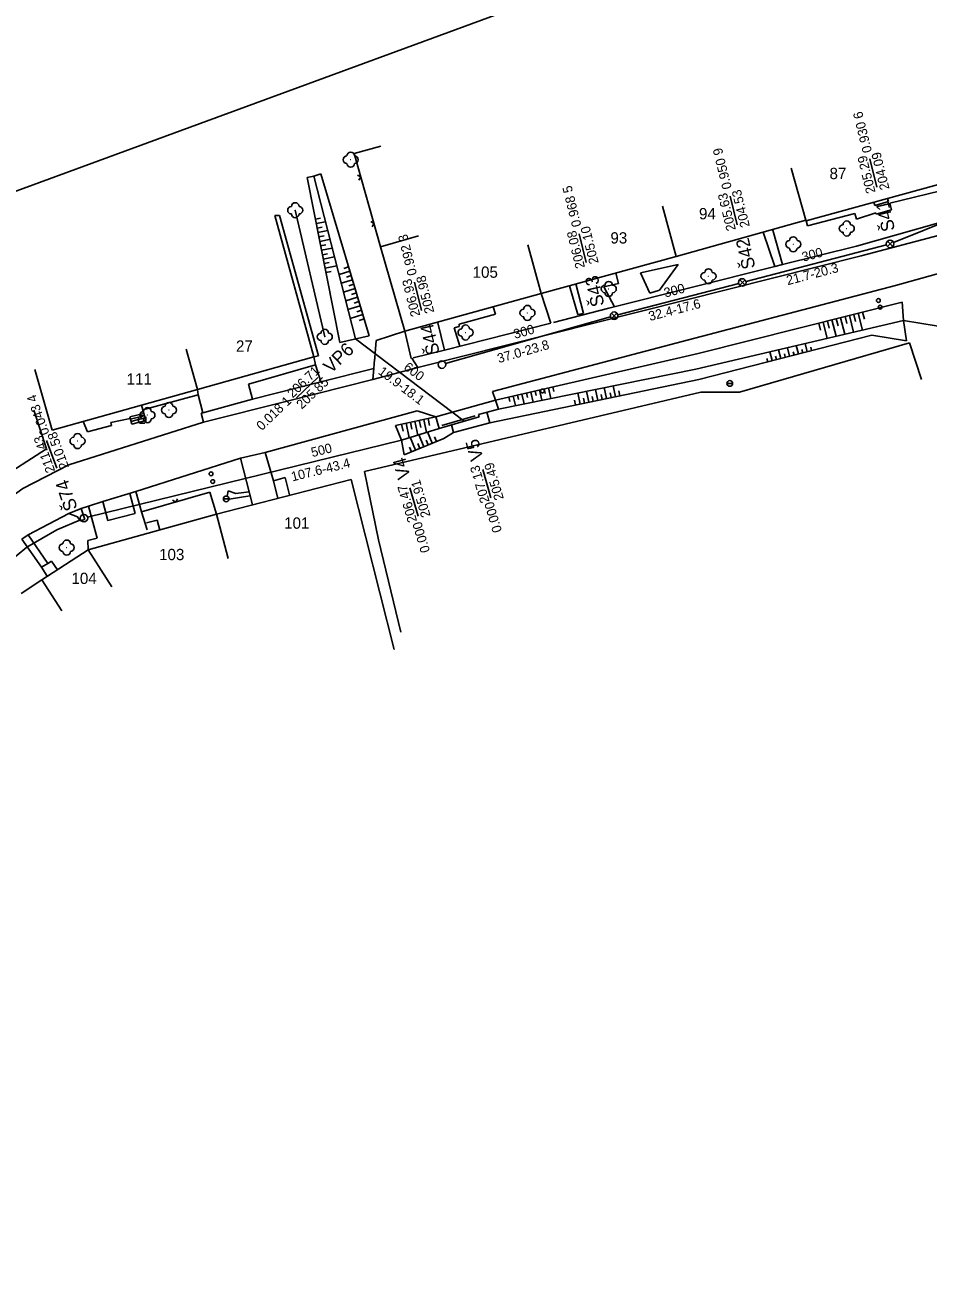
# Model space of a CAD drawing. Extents: x -574526 to -573537, y -1188297 to -1187280.
# Drawn here: x -574440.8 to -574321, y -1188129.5 to -1187965.1 of the extents above; entities that cross this region are included whole.
import ezdxf

# ---------------------------------------------------------------- set-up
doc = ezdxf.new("R2010")
doc.units = 0
for name, color, linetype in [('Vrstva 10', 7, 'Continuous'), ('Vrstva 12', 7, 'Continuous'), ('Vrstva 13', 7, 'Continuous'), ('Vrstva 14', 7, 'Continuous'), ('Vrstva 17', 7, 'Continuous'), ('Vrstva 18', 7, 'Continuous'), ('Vrstva 2', 7, 'Continuous'), ('Vrstva 21', 7, 'Continuous'), ('Vrstva 4', 7, 'Continuous'), ('Vrstva 6', 7, 'Continuous'), ('Vrstva 63', 7, 'Continuous'), ('Vrstva 7', 7, 'Continuous'), ('Vrstva 8', 7, 'Continuous'), ('Vrstva 9', 7, 'Continuous')]:
    doc.layers.add(name, color=color, linetype=linetype)

# ---------------------------------------------------------------- blocks, each defined once
blk = doc.blocks.new('3$130')
at = {"layer": 'Vrstva 8'}
blk.add_circle((0, 0), 0.001, dxfattribs=at)
for centre, start, end in [((-1, 0), 90, 270), ((0, 1), 0, 180), ((1, 0), 270, 90), ((0, -1), 180, 0)]:
    blk.add_arc(centre, 1, start, end, dxfattribs=at)
blk = doc.blocks.new('8$110')
at = {"layer": 'Vrstva 6'}
blk.add_line((-0.75, 0), (0.75, 0), dxfattribs=at)
blk.add_circle((0, 0), 0.75, dxfattribs=at)
blk = doc.blocks.new('6$010')
at = {"layer": 'Vrstva 21'}
blk.add_circle((0, 0), 0.5, dxfattribs=at)
blk = doc.blocks.new('6$091')
at = {"layer": 'Vrstva 21'}
for p, q in [((-1, 0.7), (-1, -0.7)), ((0.7, 1), (-0.7, 1)), ((1, -0.7), (1, 0.7)), ((-0.7, -1), (0.7, -1))]:
    blk.add_line(p, q, dxfattribs=at)
blk = doc.blocks.new('200')
at = {"layer": 'Vrstva 63'}
blk.add_lwpolyline([(0, 0), (210, 0), (210, 297), (0, 297), (0, 0)], close=True, dxfattribs=at)

msp = doc.modelspace()

# ---------------------------------------------------------------- linework, layer by layer
at = {"layer": 'Vrstva 10'}
for p, q in [((-574402.48, -1187985.21), (-574403.39, -1187985.39)), ((-574401.57, -1187984.87), (-574402.48, -1187985.21)), ((-574396.97, -1188006.77), (-574402.48, -1187985.21)), ((-574395.16, -1188006.36), (-574401.57, -1187984.87)), ((-574403.39, -1187985.39), (-574399.05, -1188007.24)), ((-574401.61, -1187990.77), (-574402.29, -1187990.9)), ((-574400.94, -1187991.25), (-574402.18, -1187991.49)), ((-574401.38, -1187991.95), (-574402.06, -1187992.08)), ((-574400.64, -1187992.41), (-574401.94, -1187992.67)), ((-574401.14, -1187993.12), (-574401.83, -1187993.26)), ((-574400.3, -1187993.57), (-574401.71, -1187993.85)), ((-574400.91, -1187994.3), (-574401.59, -1187994.43)), ((-574400.05, -1187994.74), (-574401.48, -1187995.03)), ((-574400.68, -1187995.48), (-574401.36, -1187995.61)), ((-574399.75, -1187995.91), (-574401.24, -1187996.2)), ((-574400.44, -1187996.65), (-574401.13, -1187996.79)), ((-574399.45, -1187997.07), (-574401.01, -1187997.38)), ((-574400.21, -1187997.83), (-574400.89, -1187997.97)), ((-574399.15, -1187998.24), (-574397.71, -1187997.81)), ((-574398.52, -1187997.42), (-574397.88, -1187997.23)), ((-574398.85, -1187999.4), (-574397.37, -1187998.96)), ((-574398.17, -1187998.57), (-574397.54, -1187998.38)), ((-574397.83, -1187999.72), (-574397.19, -1187999.53)), ((-574398.56, -1188000.56), (-574397.02, -1188000.11)), ((-574398.26, -1188001.73), (-574396.68, -1188001.26)), ((-574397.49, -1188000.87), (-574396.85, -1188000.68)), ((-574397.96, -1188002.89), (-574396.34, -1188002.41)), ((-574397.15, -1188002.02), (-574396.51, -1188001.83)), ((-574396.8, -1188003.17), (-574396.17, -1188002.98)), ((-574324.45, -1188001.92), (-574351.5, -1188008.72)), ((-574329.45, -1188004.17), (-574329.69, -1188003.23)), ((-574324.24, -1188004.33), (-574324.45, -1188001.92)), ((-574397.67, -1188004.06), (-574396, -1188003.56)), ((-574396.46, -1188004.32), (-574395.82, -1188004.13)), ((-574351.79, -1188010.78), (-574324.24, -1188004.33)), ((-574335.27, -1188005.63), (-574335.51, -1188004.7)), ((-574334.38, -1188006.71), (-574334.92, -1188004.55)), ((-574334.11, -1188005.34), (-574334.34, -1188004.41)), ((-574333.21, -1188006.43), (-574333.76, -1188004.26)), ((-574332.94, -1188005.05), (-574333.18, -1188004.11)), ((-574332.05, -1188006.16), (-574332.6, -1188003.97)), ((-574331.78, -1188004.75), (-574332.01, -1188003.82)), ((-574330.88, -1188005.88), (-574331.43, -1188003.67)), ((-574330.62, -1188004.46), (-574330.85, -1188003.53)), ((-574329.71, -1188005.61), (-574330.27, -1188003.38)), ((-574324.24, -1188004.33), (-574323.85, -1188007.05)), ((-574399.05, -1188007.24), (-574395.16, -1188006.36)), ((-574328.47, -1188006.27), (-574351.41, -1188012.16)), ((-574323.85, -1188007.05), (-574328.47, -1188006.27)), ((-574340.82, -1188008.21), (-574340.52, -1188009.37)), ((-574339.65, -1188007.94), (-574339.36, -1188009.07)), ((-574338.48, -1188007.67), (-574338.2, -1188008.77)), ((-574337.73, -1188008.17), (-574337.62, -1188008.62)), ((-574337.31, -1188007.39), (-574337.04, -1188008.47)), ((-574336.57, -1188007.87), (-574336.46, -1188008.32)), ((-574351.5, -1188008.72), (-574378.37, -1188014.89)), ((-574342.38, -1188009.36), (-574342.27, -1188009.81)), ((-574341.99, -1188008.49), (-574341.69, -1188009.66)), ((-574341.22, -1188009.06), (-574341.11, -1188009.51)), ((-574340.06, -1188008.76), (-574339.94, -1188009.21)), ((-574338.89, -1188008.47), (-574338.78, -1188008.91)), ((-574378.01, -1188016.08), (-574351.79, -1188010.78)), ((-574351.41, -1188012.16), (-574379.15, -1188017.9)), ((-574370.64, -1188013.75), (-574370.78, -1188013.15)), ((-574362.77, -1188013), (-574362.47, -1188014.45)), ((-574376.49, -1188015.09), (-574376.63, -1188014.49)), ((-574375.75, -1188015.62), (-574376.05, -1188014.36)), ((-574375.32, -1188014.82), (-574375.46, -1188014.22)), ((-574374.58, -1188015.39), (-574374.88, -1188014.09)), ((-574374.15, -1188014.55), (-574374.29, -1188013.95)), ((-574373.4, -1188015.15), (-574373.71, -1188013.82)), ((-574372.98, -1188014.28), (-574373.12, -1188013.69)), ((-574372.22, -1188014.91), (-574372.54, -1188013.55)), ((-574371.81, -1188014.01), (-574371.95, -1188013.41)), ((-574371.05, -1188014.67), (-574371.37, -1188013.28)), ((-574367.48, -1188013.95), (-574367.17, -1188015.42)), ((-574366.72, -1188014.65), (-574366.59, -1188015.3)), ((-574366.3, -1188013.71), (-574366, -1188015.18)), ((-574365.55, -1188014.4), (-574365.41, -1188015.06)), ((-574365.12, -1188013.47), (-574364.82, -1188014.93)), ((-574364.37, -1188014.16), (-574364.23, -1188014.81)), ((-574363.95, -1188013.24), (-574363.65, -1188014.69)), ((-574363.19, -1188013.92), (-574363.06, -1188014.57)), ((-574362.02, -1188013.67), (-574361.88, -1188014.33)), ((-574367.89, -1188014.89), (-574367.76, -1188015.54)), ((-574391.67, -1188018.24), (-574386.32, -1188017.11)), ((-574390.65, -1188019.01), (-574390.85, -1188018.07)), ((-574389.85, -1188019.88), (-574390.26, -1188017.94)), ((-574389.48, -1188018.76), (-574389.67, -1188017.82)), ((-574388.7, -1188019.53), (-574389.09, -1188017.69)), ((-574388.3, -1188018.51), (-574388.5, -1188017.57)), ((-574387.55, -1188019.17), (-574387.91, -1188017.45)), ((-574387.13, -1188018.26), (-574387.33, -1188017.32)), ((-574390.88, -1188020.2), (-574391.67, -1188018.24)), ((-574390.88, -1188020.2), (-574385.88, -1188018.65)), ((-574388.54, -1188019.47), (-574387.89, -1188021.07)), ((-574387.39, -1188019.12), (-574386.78, -1188020.61)), ((-574385.23, -1188019.98), (-574383.95, -1188019.18)), ((-574390.5, -1188022.14), (-574390.88, -1188020.2)), ((-574390.5, -1188022.14), (-574385.23, -1188019.98)), ((-574389.81, -1188021.12), (-574389.55, -1188021.75)), ((-574389.69, -1188019.83), (-574389, -1188021.53)), ((-574388.7, -1188020.67), (-574388.44, -1188021.3)), ((-574387.59, -1188020.22), (-574387.33, -1188020.84)), ((-574386.48, -1188019.76), (-574386.22, -1188020.39))]:
    msp.add_line(p, q, dxfattribs=at)
at = {"layer": 'Vrstva 13'}
for p, q in [((-574327.81, -1187986.66), (-574328.74, -1187982.88)), ((-574346.33, -1187991.65), (-574347.27, -1187987.86)), ((-574366.36, -1187996.64), (-574367.3, -1187992.85)), ((-574388.21, -1188003.03), (-574389.15, -1187999.25)), ((-574404.78, -1188014.61), (-574401.97, -1188011.9)), ((-574436.61, -1188023.92), (-574437.94, -1188020.25)), ((-574378.99, -1188027.84), (-574380.09, -1188024.1)), ((-574388.66, -1188030.29), (-574389.76, -1188026.54))]:
    msp.add_line(p, q, dxfattribs=at)
at = {"layer": 'Vrstva 17'}
for p, q in [((-574326.39, -1187994.53), (-574325.69, -1187993.82)), ((-574326.39, -1187993.82), (-574325.69, -1187994.53)), ((-574345.99, -1187999.64), (-574345.28, -1187998.94)), ((-574345.99, -1187998.94), (-574345.28, -1187999.64)), ((-574363, -1188004.05), (-574362.29, -1188003.35)), ((-574363, -1188003.35), (-574362.29, -1188004.05))]:
    msp.add_line(p, q, dxfattribs=at)
at = {"layer": 'Vrstva 2'}
for p, q in [((-574325.58, -1187993.99), (-574296.46, -1187982.19)), ((-574345.15, -1187999.16), (-574326.52, -1187994.3)), ((-574362.16, -1188003.57), (-574346.12, -1187999.41)), ((-574385.02, -1188010.05), (-574363.13, -1188003.84)), ((-574324.24, -1188004.33), (-574317.75, -1188005.4)), ((-574396.97, -1188006.77), (-574382.54, -1188017.69)), ((-574432.51, -1188030.43), (-574390.88, -1188020.2))]:
    msp.add_line(p, q, dxfattribs=at)
msp.add_lwpolyline([(-574466.04, -1188068.94), (-574458.4, -1188054.44), (-574455.1, -1188048.91), (-574451.58, -1188044.6), (-574447.05, -1188039.72), (-574440.59, -1188034.41), (-574436.57, -1188032.11), (-574433.45, -1188030.75)], dxfattribs=at)
at = {"layer": 'Vrstva 4'}
for p, q in [((-574401.04, -1188006.5), (-574404.96, -1187989.71)), ((-574354.16, -1187996.91), (-574359.15, -1187998.03)), ((-574359.15, -1187998.03), (-574357.93, -1188000.73)), ((-574356.61, -1188000.31), (-574354.16, -1187996.91)), ((-574357.93, -1188000.73), (-574356.61, -1188000.31)), ((-574346.02, -1188013.83), (-574323.46, -1188007.29)), ((-574323.46, -1188007.29), (-574321.88, -1188012.16)), ((-574395.77, -1188024.35), (-574351.16, -1188013.86)), ((-574351.16, -1188013.86), (-574346.02, -1188013.83)), ((-574437.95, -1188021.35), (-574439.66, -1188016.24)), ((-574449.5, -1188028.77), (-574437.95, -1188021.35)), ((-574393.9, -1188033.41), (-574395.77, -1188024.35)), ((-574393.9, -1188033.41), (-574390.96, -1188045.67))]:
    msp.add_line(p, q, dxfattribs=at)
at = {"layer": 'Vrstva 6'}
for p, q in [((-574393.6, -1187981.21), (-574397.14, -1187982.21)), ((-574393.65, -1187994.55), (-574397.14, -1187982.21)), ((-574326.38, -1187988.15), (-574326.26, -1187988.55)), ((-574328.19, -1187988.65), (-574328.06, -1187989.08)), ((-574328.06, -1187989.08), (-574326.26, -1187988.55)), ((-574371.05, -1188004.69), (-574372.31, -1188000.76)), ((-574390.44, -1188005.74), (-574389.57, -1188009.36)), ((-574401.58, -1188012.49), (-574402.26, -1188010.22)), ((-574410.63, -1188014.75), (-574401.58, -1188012.49)), ((-574378.01, -1188016.08), (-574380.65, -1188016.82)), ((-574378.37, -1188014.89), (-574378.01, -1188016.08)), ((-574425.06, -1188016.67), (-574426.92, -1188017.13)), ((-574426.92, -1188017.13), (-574426.66, -1188018.07)), ((-574424.99, -1188016.96), (-574426.85, -1188017.42)), ((-574424.91, -1188017.25), (-574426.77, -1188017.71)), ((-574424.8, -1188017.61), (-574426.66, -1188018.07)), ((-574425.06, -1188016.67), (-574424.8, -1188017.61)), ((-574386.32, -1188017.11), (-574385.88, -1188018.65)), ((-574380.56, -1188017.13), (-574385.88, -1188018.65)), ((-574385.49, -1188018.26), (-574381.08, -1188017)), ((-574383.95, -1188019.18), (-574379.15, -1188017.9)), ((-574380.65, -1188016.82), (-574380.56, -1188017.13)), ((-574379.52, -1188016.5), (-574379.15, -1188017.9)), ((-574384.22, -1188018.17), (-574383.95, -1188019.18)), ((-574425.36, -1188029.7), (-574416.27, -1188027.11)), ((-574416.27, -1188027.11), (-574415.39, -1188030.02)), ((-574424.62, -1188032.08), (-574425.36, -1188029.7)), ((-574441.31, -1188040.56), (-574438.57, -1188038.71))]:
    msp.add_line(p, q, dxfattribs=at)
for points in [[(-574396.51, -1187985.73), (-574396.27, -1187985.29), (-574396.7, -1187985.05)], [(-574394.76, -1187991.9), (-574394.52, -1187991.47), (-574394.95, -1187991.22)], [(-574421.25, -1188028.16), (-574420.82, -1188028.41), (-574420.57, -1188027.97)]]:
    msp.add_lwpolyline(points, dxfattribs=at)
at = {"layer": 'Vrstva 7'}
for p, q in [((-574339.16, -1187984.13), (-574337.23, -1187991.01)), ((-574317.85, -1187985.82), (-574337.19, -1187991.11)), ((-574356.24, -1187989.18), (-574354.41, -1187995.83)), ((-574407.66, -1187990.42), (-574402.49, -1188009.14)), ((-574337.23, -1187991.01), (-574354.41, -1187995.83)), ((-574337.19, -1187991.11), (-574337.23, -1187991.01)), ((-574388.62, -1187993.11), (-574393.65, -1187994.55)), ((-574390.44, -1188005.74), (-574393.65, -1187994.55)), ((-574374.09, -1187994.29), (-574372.31, -1188000.76)), ((-574354.41, -1187995.83), (-574372.31, -1188000.76)), ((-574372.31, -1188000.76), (-574390.44, -1188005.74)), ((-574419.41, -1188008.12), (-574417.91, -1188013.49)), ((-574402.49, -1188009.14), (-574417.91, -1188013.49)), ((-574439.5, -1188010.84), (-574437.19, -1188018.89)), ((-574417.91, -1188013.49), (-574437.19, -1188018.89)), ((-574415.39, -1188030.02), (-574397.53, -1188025.42)), ((-574391.85, -1188047.95), (-574397.53, -1188025.42)), ((-574432.42, -1188034.76), (-574415.39, -1188030.02)), ((-574413.88, -1188035.89), (-574415.39, -1188030.02)), ((-574438.57, -1188038.71), (-574432.42, -1188034.76)), ((-574429.28, -1188039.65), (-574432.42, -1188034.76)), ((-574435.92, -1188042.83), (-574438.57, -1188038.71))]:
    msp.add_line(p, q, dxfattribs=at)
at = {"layer": 'Vrstva 8'}
for centre in [(-574326.04, -1187994.18), (-574345.64, -1187999.29), (-574362.65, -1188003.7), (-574385.5, -1188010.19), (-574432.99, -1188030.55)]:
    msp.add_circle(centre, 0.5, dxfattribs=at)
at = {"layer": 'Vrstva 9'}
for p, q in [((-574317.7, -1187986.76), (-574326.05, -1187988.76)), ((-574330.72, -1187990.14), (-574336.99, -1187991.78)), ((-574330.51, -1187990.89), (-574330.72, -1187990.14)), ((-574327.94, -1187990.08), (-574330.51, -1187990.89)), ((-574327.87, -1187990.24), (-574327.94, -1187990.08)), ((-574325.84, -1187989.66), (-574327.87, -1187990.24)), ((-574326.05, -1187988.76), (-574325.84, -1187989.66)), ((-574407.05, -1187990.4), (-574407.66, -1187990.42)), ((-574401.86, -1188009.01), (-574407.05, -1187990.4)), ((-574336.99, -1187991.78), (-574337.19, -1187991.11)), ((-574315.93, -1187990.34), (-574330.49, -1187994.49)), ((-574341.33, -1187997.18), (-574342.88, -1187992.63)), ((-574341.61, -1187992.34), (-574340.32, -1187996.93)), ((-574330.49, -1187994.49), (-574340.32, -1187996.93)), ((-574329.89, -1187995.75), (-574388.71, -1188010.59)), ((-574325.32, -1187999.69), (-574312.62, -1187996.17)), ((-574341.33, -1187997.18), (-574363.37, -1188002.71)), ((-574362.42, -1187998.04), (-574362.05, -1187999.43)), ((-574340.32, -1187996.93), (-574341.33, -1187997.18)), ((-574367.48, -1188003.54), (-574368.59, -1187999.74)), ((-574367.71, -1187999.49), (-574366.7, -1188003.41)), ((-574362.05, -1187999.43), (-574364.01, -1187999.87)), ((-574362.61, -1188002.52), (-574364.01, -1187999.87)), ((-574352.77, -1188006.89), (-574325.32, -1187999.69)), ((-574378.68, -1188002.51), (-574378.41, -1188003.49)), ((-574363.37, -1188002.71), (-574370.71, -1188004.59)), ((-574386.03, -1188004.63), (-574385.14, -1188008.29)), ((-574378.41, -1188003.49), (-574383.22, -1188004.83)), ((-574383.19, -1188005.15), (-574383.22, -1188004.83)), ((-574371.05, -1188004.69), (-574382.38, -1188007.55)), ((-574366.7, -1188003.41), (-574367.48, -1188003.54)), ((-574390.44, -1188005.74), (-574394.21, -1188006.99)), ((-574383.86, -1188005.3), (-574383.19, -1188005.15)), ((-574383.86, -1188005.3), (-574383.1, -1188007.74)), ((-574394.21, -1188006.99), (-574394.46, -1188009.79)), ((-574382.38, -1188007.55), (-574385.14, -1188008.29)), ((-574378.78, -1188013.74), (-574352.77, -1188006.89)), ((-574402.49, -1188009.14), (-574401.86, -1188009.01)), ((-574402.49, -1188009.14), (-574402.26, -1188010.22)), ((-574394.43, -1188009.48), (-574394.54, -1188010.7)), ((-574388.71, -1188010.59), (-574389.5, -1188009.34)), ((-574385.14, -1188008.29), (-574389.32, -1188009.29)), ((-574402.26, -1188010.22), (-574411.17, -1188012.78)), ((-574394.54, -1188010.7), (-574401.58, -1188012.49)), ((-574394.65, -1188012.15), (-574388.71, -1188010.59)), ((-574394.54, -1188010.7), (-574394.65, -1188012.15)), ((-574411.17, -1188012.78), (-574410.63, -1188014.75)), ((-574394.65, -1188012.15), (-574406.04, -1188015.02)), ((-574425.19, -1188016.19), (-574417.83, -1188014.21)), ((-574417.83, -1188014.21), (-574417.91, -1188013.49)), ((-574417.83, -1188014.21), (-574417.22, -1188016.57)), ((-574410.63, -1188014.75), (-574417.22, -1188016.57)), ((-574378.37, -1188014.89), (-574378.78, -1188013.74)), ((-574425.06, -1188016.67), (-574425.36, -1188015.58)), ((-574406.04, -1188015.02), (-574417.13, -1188017.82)), ((-574408.96, -1188021.82), (-574388.76, -1188016.33)), ((-574388.76, -1188016.33), (-574386.32, -1188017.11)), ((-574378.37, -1188014.89), (-574386.32, -1188017.11)), ((-574417.13, -1188017.82), (-574435.01, -1188023.49)), ((-574433.08, -1188017.74), (-574432.52, -1188019.1)), ((-574429.44, -1188017.88), (-574426.87, -1188017.32)), ((-574429.33, -1188018.28), (-574429.44, -1188017.88)), ((-574417.42, -1188016.63), (-574417.22, -1188016.57)), ((-574417.42, -1188016.63), (-574417.13, -1188017.82)), ((-574432.52, -1188019.1), (-574429.33, -1188018.28)), ((-574426.13, -1188027.03), (-574412.2, -1188022.6)), ((-574412.2, -1188022.6), (-574408.96, -1188021.82)), ((-574412.2, -1188022.6), (-574410.64, -1188028.8)), ((-574408.96, -1188021.82), (-574407.85, -1188025.58)), ((-574407.85, -1188025.58), (-574406.28, -1188025.17)), ((-574407.85, -1188025.58), (-574407.28, -1188027.93)), ((-574406.28, -1188025.17), (-574405.73, -1188027.45)), ((-574430.5, -1188028.34), (-574426.13, -1188027.03)), ((-574426.18, -1188029.91), (-574426.92, -1188027.27)), ((-574426.13, -1188027.03), (-574425.36, -1188029.7)), ((-574413.98, -1188027.63), (-574413.85, -1188026.93)), ((-574413.85, -1188026.93), (-574412.84, -1188027.3)), ((-574411, -1188027.59), (-574413.73, -1188028.04)), ((-574412.84, -1188027.3), (-574411.08, -1188027.05)), ((-574435.02, -1188029.92), (-574433.37, -1188029.27)), ((-574433.37, -1188029.27), (-574432.41, -1188028.96)), ((-574432.88, -1188030.73), (-574433.37, -1188029.27)), ((-574432.41, -1188028.96), (-574430.5, -1188028.34)), ((-574432.41, -1188028.96), (-574431.24, -1188033.19)), ((-574430.5, -1188028.34), (-574429.84, -1188030.88)), ((-574440.39, -1188032.74), (-574435.02, -1188029.92)), ((-574435.02, -1188029.92), (-574433.86, -1188030.38)), ((-574433.86, -1188030.38), (-574433.49, -1188030.91)), ((-574433.49, -1188030.91), (-574432.88, -1188030.73)), ((-574429.84, -1188030.88), (-574426.18, -1188029.91)), ((-574424.7, -1188031.15), (-574423.26, -1188030.8)), ((-574422.94, -1188032.12), (-574423.26, -1188030.8)), ((-574441.24, -1188033.33), (-574440.39, -1188032.74)), ((-574437.78, -1188036.55), (-574440.39, -1188032.74)), ((-574441.24, -1188033.33), (-574438.61, -1188037.07)), ((-574431.24, -1188033.19), (-574432.46, -1188033.5)), ((-574432.46, -1188033.5), (-574432.42, -1188034.76)), ((-574438.61, -1188037.07), (-574437.78, -1188036.55)), ((-574438.61, -1188037.07), (-574437.88, -1188038.26)), ((-574437.78, -1188036.55), (-574437.28, -1188036.27)), ((-574437.28, -1188036.27), (-574436.52, -1188037.39))]:
    msp.add_line(p, q, dxfattribs=at)
for points in [[(-574329.89, -1187995.75), (-574319.49, -1187993.01), (-574312.77, -1187990.72), (-574305.58, -1187987.62), (-574299.35, -1187984.41)], [(-574435.01, -1188023.49), (-574441.08, -1188026.6), (-574445.67, -1188029.88), (-574451.55, -1188034.72), (-574457.77, -1188041.29), (-574463.27, -1188049.05), (-574466.91, -1188055.57)]]:
    msp.add_lwpolyline(points, dxfattribs=at)

# ---------------------------------------------------------------- block references
at = {"layer": 'Vrstva 21', "xscale": 0.5, "yscale": 0.5}
for name, p in [('6$010', (-574327.59, -1188001.68)), ('6$010', (-574327.36, -1188002.57)), ('6$010', (-574372.17, -1188013.68)), ('6$091', (-574425.27, -1188017.47)), ('6$010', (-574416.13, -1188024.67)), ('6$010', (-574415.91, -1188025.7))]:
    msp.add_blockref(name, p, dxfattribs=at)
at = {"layer": 'Vrstva 4', "xscale": 0.5, "yscale": 0.5}
for p in [(-574397.6, -1187983.01), (-574404.96, -1187989.71), (-574331.78, -1187992.14), (-574338.88, -1187994.23), (-574350.13, -1187998.47), (-574363.36, -1188000.15), (-574374.15, -1188003.33), (-574382.36, -1188005.93), (-574401.04, -1188006.5), (-574424.57, -1188016.89), (-574421.71, -1188016.21), (-574433.84, -1188020.33), (-574435.28, -1188034.45)]:
    msp.add_blockref('3$130', p, dxfattribs=at)
at = {"layer": 'Vrstva 6', "xscale": 0.5, "yscale": 0.5}
for p in [(-574347.31, -1188012.69), (-574414.11, -1188027.99)]:
    msp.add_blockref('8$110', p, dxfattribs=at)
at = {"layer": 'Vrstva 63', "xscale": 2.9999999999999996, "rotation": 20.160475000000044}
msp.add_blockref('200', (-574423.39, -1188296.69), dxfattribs=at)

# ---------------------------------------------------------------- texts
at = {"layer": 'Vrstva 12'}
for s, p in [('87', (-574334.07, -1187985.59)), ('94', (-574351.39, -1187990.92)), ('93', (-574363.14, -1187994.13)), ('105', (-574381.42, -1187998.67)), ('27', (-574412.82, -1188008.48)), ('111', (-574427.33, -1188012.85)), ('101', (-574406.43, -1188031.95)), ('103', (-574423.02, -1188036.12)), ('104', (-574434.65, -1188039.28))]:
    msp.add_text(s, height=1.5, dxfattribs=at).set_placement(p)
at = {"layer": 'Vrstva 13'}
for s, rotation, p in [('0.930 6', 103.9053, (-574328.42, -1187981.93)), ('0.950 9', 103.9053, (-574347.03, -1187986.76)), ('205.29', 103.9053, (-574327.95, -1187987.32)), ('204.09', 103.9053, (-574326.1, -1187986.86)), ('0.968 5', 103.9053, (-574366.98, -1187991.76)), ('205.63', 103.9053, (-574346.48, -1187992.29)), ('204.53', 103.9053, (-574344.63, -1187991.84)), ('0.992 3', 103.9053, (-574388.79, -1187998.21)), ('206.08', 103.9053, (-574366.51, -1187997.28)), ('205.10', 103.9053, (-574364.69, -1187996.68)), ('206.93', 103.9053, (-574388.36, -1188003.67)), ('205.98', 103.9053, (-574386.5, -1188003.23)), ('206.71', 43.884, (-574405.3, -1188014.69)), ('205.85', 43.884, (-574404.09, -1188016.18)), ('0.043 4', 109.9876, (-574437.54, -1188019.28)), ('0.018 1', 43.884, (-574409.39, -1188019.01)), ('211.43', 109.9876, (-574436.79, -1188024.28)), ('210.58', 109.9876, (-574434.95, -1188023.78)), ('207.13', 106.3973, (-574379.15, -1188028.35)), ('205.49', 106.3973, (-574377.27, -1188027.96)), ('205.91', 106.3973, (-574386.99, -1188030.25)), ('206.47', 106.3973, (-574388.78, -1188030.93)), ('0.000', 106.3973, (-574377.52, -1188032.26)), ('0.000', 106.3973, (-574387.06, -1188034.93))]:
    msp.add_text(s, height=1.25, rotation=rotation, dxfattribs=at).set_placement(p)
at = {"layer": 'Vrstva 14'}
for s, height, rotation, p in [('300', 1.25, 14.6198, (-574337.56, -1187996.54)), ('21.7-20.3', 1.25, 14.6198, (-574339.62, -1187999.66)), ('300', 1.249, 14.5374, (-574355.86, -1188001.3)), ('32.4-17.6', 1.249, 14.5374, (-574357.9, -1188004.41)), ('300', 1.25, 15.8558, (-574375.8, -1188006.78)), ('37.0-23.8', 1.25, 15.8558, (-574377.95, -1188010)), ('19.9-18.1', 1.25, 322.8774, (-574394.05, -1188011.33)), ('600', 1.25, 322.8774, (-574390.67, -1188010.75)), ('500', 1.25, 13.8063, (-574402.69, -1188022.46)), ('107.6-43.4', 1.25, 13.8063, (-574405.33, -1188025.68))]:
    msp.add_text(s, height=height, rotation=rotation, dxfattribs=at).set_placement(p)
at = {"layer": 'Vrstva 18'}
for s, rotation, p in [('Š41', 102.9832, (-574325.36, -1187992.32)), ('Š42', 102.9832, (-574343.89, -1187997.31)), ('Š43', 102.9832, (-574363.92, -1188002.29)), ('Š44', 102.9832, (-574385.77, -1188008.69)), ('VP6', 43.884, (-574400.22, -1188011.44)), ('V5', 105.4752, (-574379.96, -1188022.67)), ('V4', 105.4752, (-574389.63, -1188025.11)), ('Š74', 109.0655, (-574433.81, -1188029.23))]:
    msp.add_text(s, height=1.75, rotation=rotation, dxfattribs=at).set_placement(p)

doc.saveas('drawing.dxf')
